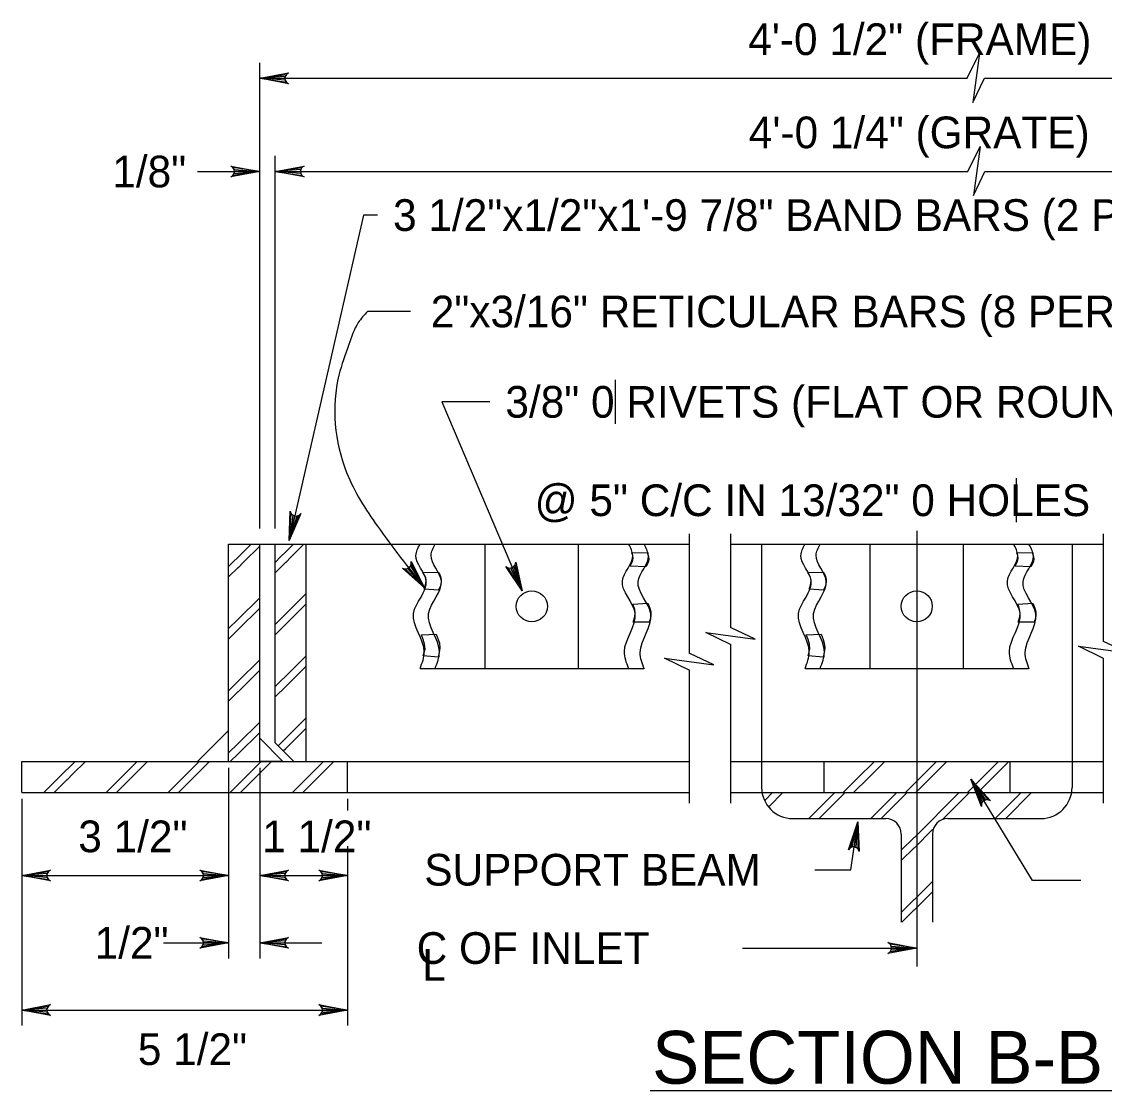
# Model space of a CAD drawing. Extents: x 0.71 to 8.05, y -5.67 to 4.31.
# Drawn here: x 0.931 to 2.982, y -3.979 to -1.955 of the extents above; entities that cross this region are included whole.
import ezdxf

# ---------------------------------------------------------------- set-up
doc = ezdxf.new("R2010")
doc.units = 0
for name, color, linetype in [('DETL-DIMS', 7, 'Continuous'), ('DETL-LINE', 7, 'Continuous'), ('DETL-NOTE', 7, 'Continuous'), ('DETL-PATT', 7, 'Continuous'), ('DETL-TITL', 7, 'Continuous')]:
    doc.layers.add(name, color=color, linetype=linetype)

msp = doc.modelspace()

# ---------------------------------------------------------------- linework, layer by layer
at = {"layer": 'DETL-DIMS'}
for p, q in [((1.382, -2.9151), (1.382, -2.0328)), ((1.382, -2.0622), (2.7227, -2.0622)), ((2.755, -2.0622), (3.8721, -2.0622)), ((1.4114, -2.9151), (1.4114, -2.2093)), ((1.2643, -2.2387), (1.382, -2.2387)), ((1.4114, -2.2387), (2.7238, -2.2387)), ((2.7562, -2.2387), (3.8427, -2.2387)), ((1.5786, -2.3212), (1.4378, -2.9377)), ((1.605, -2.3212), (1.5786, -2.3212)), ((1.6677, -2.5038), (1.5862, -2.5038)), ((1.8181, -2.6749), (1.7268, -2.6749)), ((1.7268, -2.6749), (1.8794, -3.033)), ((2.627, -2.9192), (2.627, -3.7442)), ((1.3231, -3.3681), (1.3231, -3.7289)), ((1.382, -3.3681), (1.382, -3.7289)), ((2.8464, -3.5814), (2.7297, -3.3893)), ((0.931, -3.4269), (0.931, -3.8563)), ((1.5486, -3.4269), (1.5486, -3.4486)), ((2.5023, -3.5611), (2.5155, -3.4706)), ((1.5486, -3.5162), (1.5486, -3.6334)), ((2.4338, -3.5611), (2.5023, -3.5611)), ((0.931, -3.572), (1.3231, -3.572)), ((1.382, -3.572), (1.5486, -3.572)), ((2.9376, -3.5814), (2.8462, -3.5814)), ((1.5486, -3.6334), (1.5486, -3.8563)), ((1.2, -3.6995), (1.3231, -3.6995)), ((1.382, -3.6995), (1.4996, -3.6995)), ((2.297, -3.7094), (2.627, -3.7094)), ((0.931, -3.8269), (1.5486, -3.8269))]:
    msp.add_line(p, q, dxfattribs=at)
for points in [[(2.7227, -2.0622), (2.746, -2.0145), (2.7333, -2.1078), (2.755, -2.0622)], [(1.382, -2.0622), (1.4368, -2.0519), (1.4326, -2.0548), (1.4304, -2.0585), (1.4297, -2.0622), (1.4304, -2.0659), (1.4326, -2.0695), (1.4368, -2.0725), (1.382, -2.0622), (1.4326, -2.0695), (1.4304, -2.0659), (1.382, -2.0622), (1.4297, -2.0622), (1.4304, -2.0585), (1.382, -2.0622), (1.4326, -2.0548)], [(2.7238, -2.2388), (2.7471, -2.1911), (2.7344, -2.2844), (2.7561, -2.2388)], [(1.382, -2.2387), (1.3271, -2.2489), (1.3313, -2.246), (1.3335, -2.2423), (1.3342, -2.2387), (1.3335, -2.235), (1.3313, -2.2313), (1.3271, -2.2284), (1.382, -2.2387), (1.3313, -2.2313), (1.3335, -2.235), (1.382, -2.2387), (1.3342, -2.2387), (1.3335, -2.2423), (1.382, -2.2387), (1.3313, -2.246)], [(1.4114, -2.2387), (1.4662, -2.2284), (1.462, -2.2313), (1.4598, -2.235), (1.4592, -2.2387), (1.4598, -2.2423), (1.462, -2.246), (1.4662, -2.2489), (1.4114, -2.2387), (1.462, -2.246), (1.4598, -2.2423), (1.4114, -2.2387), (1.4592, -2.2387), (1.4598, -2.235), (1.4114, -2.2387), (1.462, -2.2313)], [(1.4378, -2.9377), (1.44, -2.882), (1.4419, -2.8868), (1.445, -2.8897), (1.4484, -2.8911), (1.4521, -2.8914), (1.4562, -2.89), (1.46, -2.8866), (1.4378, -2.9377), (1.4562, -2.89), (1.4521, -2.8914), (1.4378, -2.9377), (1.4484, -2.8911), (1.445, -2.8897), (1.4378, -2.9377), (1.4419, -2.8868)], [(1.6941, -3.0271), (1.6527, -2.9897), (1.6576, -2.9913), (1.6618, -2.9908), (1.6651, -2.9891), (1.6677, -2.9863), (1.6693, -2.9824), (1.669, -2.9772), (1.6941, -3.0271), (1.6693, -2.9824), (1.6677, -2.9863), (1.6941, -3.0271), (1.6651, -2.9891), (1.6618, -2.9908), (1.6941, -3.0271), (1.6576, -2.9913)], [(1.8794, -3.033), (1.8485, -2.9866), (1.8528, -2.9894), (1.857, -2.9899), (1.8607, -2.9891), (1.8638, -2.987), (1.8663, -2.9836), (1.8674, -2.9786), (1.8794, -3.033), (1.8663, -2.9836), (1.8638, -2.987), (1.8794, -3.033), (1.8607, -2.9891), (1.857, -2.9899), (1.8794, -3.033), (1.8528, -2.9894)], [(2.7297, -3.3893), (2.7669, -3.4308), (2.7622, -3.4287), (2.7579, -3.4287), (2.7545, -3.4301), (2.7517, -3.4325), (2.7497, -3.4363), (2.7493, -3.4414), (2.7297, -3.3893), (2.7497, -3.4363), (2.7517, -3.4325), (2.7297, -3.3893), (2.7545, -3.4301), (2.7579, -3.4287), (2.7297, -3.3893), (2.7622, -3.4287)], [(2.5155, -3.4706), (2.5177, -3.5263), (2.5154, -3.5217), (2.5121, -3.519), (2.5086, -3.5178), (2.5048, -3.5179), (2.5009, -3.5196), (2.4974, -3.5233), (2.5155, -3.4706), (2.5009, -3.5196), (2.5048, -3.5179), (2.5155, -3.4706), (2.5086, -3.5178), (2.5121, -3.519), (2.5155, -3.4706), (2.5154, -3.5217)], [(0.931, -3.572), (0.9858, -3.5617), (0.9816, -3.5646), (0.9794, -3.5683), (0.9788, -3.572), (0.9794, -3.5757), (0.9816, -3.5794), (0.9858, -3.5823), (0.931, -3.572), (0.9816, -3.5794), (0.9794, -3.5757), (0.931, -3.572), (0.9788, -3.572), (0.9794, -3.5683), (0.931, -3.572), (0.9816, -3.5646)], [(1.3231, -3.572), (1.2683, -3.5823), (1.2725, -3.5794), (1.2747, -3.5757), (1.2753, -3.572), (1.2747, -3.5683), (1.2725, -3.5646), (1.2683, -3.5617), (1.3231, -3.572), (1.2725, -3.5646), (1.2747, -3.5683), (1.3231, -3.572), (1.2753, -3.572), (1.2747, -3.5757), (1.3231, -3.572), (1.2725, -3.5794)], [(1.382, -3.572), (1.4368, -3.5617), (1.4326, -3.5646), (1.4304, -3.5683), (1.4297, -3.572), (1.4304, -3.5757), (1.4326, -3.5794), (1.4368, -3.5823), (1.382, -3.572), (1.4326, -3.5794), (1.4304, -3.5757), (1.382, -3.572), (1.4297, -3.572), (1.4304, -3.5683), (1.382, -3.572), (1.4326, -3.5646)], [(1.5486, -3.572), (1.4938, -3.5823), (1.498, -3.5794), (1.5002, -3.5757), (1.5008, -3.572), (1.5002, -3.5683), (1.498, -3.5646), (1.4938, -3.5617), (1.5486, -3.572), (1.498, -3.5646), (1.5002, -3.5683), (1.5486, -3.572), (1.5008, -3.572), (1.5002, -3.5757), (1.5486, -3.572), (1.498, -3.5794)], [(1.3231, -3.6995), (1.2683, -3.7097), (1.2725, -3.7068), (1.2747, -3.7031), (1.2753, -3.6995), (1.2747, -3.6958), (1.2725, -3.6921), (1.2683, -3.6892), (1.3231, -3.6995), (1.2725, -3.6921), (1.2747, -3.6958), (1.3231, -3.6995), (1.2753, -3.6995), (1.2747, -3.7031), (1.3231, -3.6995), (1.2725, -3.7068)], [(1.382, -3.6995), (1.4368, -3.6892), (1.4326, -3.6921), (1.4304, -3.6958), (1.4297, -3.6995), (1.4304, -3.7031), (1.4326, -3.7068), (1.4368, -3.7097), (1.382, -3.6995), (1.4326, -3.7068), (1.4304, -3.7031), (1.382, -3.6995), (1.4297, -3.6995), (1.4304, -3.6958), (1.382, -3.6995), (1.4326, -3.6921)], [(2.627, -3.7094), (2.5722, -3.7197), (2.5764, -3.7167), (2.5786, -3.7131), (2.5793, -3.7094), (2.5786, -3.7057), (2.5764, -3.702), (2.5722, -3.6991), (2.627, -3.7094), (2.5764, -3.702), (2.5786, -3.7057), (2.627, -3.7094), (2.5793, -3.7094), (2.5786, -3.7131), (2.627, -3.7094), (2.5764, -3.7167)], [(0.931, -3.8269), (0.9858, -3.8166), (0.9816, -3.8195), (0.9794, -3.8232), (0.9788, -3.8269), (0.9794, -3.8306), (0.9816, -3.8343), (0.9858, -3.8372), (0.931, -3.8269), (0.9816, -3.8343), (0.9794, -3.8306), (0.931, -3.8269), (0.9788, -3.8269), (0.9794, -3.8232), (0.931, -3.8269), (0.9816, -3.8195)], [(1.5486, -3.8269), (1.4938, -3.8372), (1.498, -3.8343), (1.5002, -3.8306), (1.5008, -3.8269), (1.5002, -3.8232), (1.498, -3.8195), (1.4938, -3.8166), (1.5486, -3.8269), (1.498, -3.8195), (1.5002, -3.8232), (1.5486, -3.8269), (1.5008, -3.8269), (1.5002, -3.8306), (1.5486, -3.8269), (1.498, -3.8343)]]:
    msp.add_lwpolyline(points, dxfattribs=at)
msp.add_spline([(1.5862, -2.5038), (1.5688, -2.5249), (1.5506, -2.5666), (1.5321, -2.6241), (1.5467, -2.8089), (1.6053, -2.9106), (1.6941, -3.0271)], degree=3, dxfattribs=at)
at = {"layer": 'DETL-LINE'}
for p, q in [((2.1957, -2.9249), (2.1957, -3.1516)), ((2.2741, -2.9249), (2.2741, -3.1027)), ((2.98, -2.9249), (2.98, -3.1291)), ((1.3231, -3.3563), (1.3231, -2.9445)), ((1.3231, -2.9445), (2.1957, -2.9445)), ((1.382, -3.3563), (1.382, -2.9445)), ((1.4114, -3.321), (1.4114, -2.9445)), ((1.4702, -3.3563), (1.4702, -2.9445)), ((1.8094, -3.1798), (1.8094, -2.9445)), ((1.9859, -3.1798), (1.9859, -2.9445)), ((2.2741, -2.9445), (2.98, -2.9445)), ((2.3329, -2.9445), (2.3329, -3.4053)), ((2.5388, -3.1798), (2.5388, -2.9445)), ((2.7153, -3.1798), (2.7153, -2.9445)), ((2.9212, -2.9445), (2.9212, -3.4053)), ((2.2741, -3.1352), (2.2741, -3.4347)), ((2.98, -3.1612), (2.98, -3.4347)), ((1.6859, -3.1798), (2.1094, -3.1798)), ((2.1957, -3.1834), (2.1957, -3.4347)), ((2.4153, -3.1798), (2.8388, -3.1798)), ((1.4467, -3.3563), (1.4114, -3.321)), ((0.931, -3.4151), (0.931, -3.3563)), ((0.931, -3.3563), (2.1957, -3.3563)), ((1.5486, -3.4151), (1.5486, -3.3563)), ((2.2741, -3.3563), (2.98, -3.3563)), ((2.4506, -3.3563), (2.4506, -3.4151)), ((2.8035, -3.3563), (2.8035, -3.4151)), ((0.931, -3.4151), (2.1957, -3.4151)), ((2.2741, -3.4151), (2.98, -3.4151)), ((2.3918, -3.4642), (2.5682, -3.4642)), ((2.6859, -3.4642), (2.8623, -3.4642)), ((2.5976, -3.4936), (2.5976, -3.6602)), ((2.6565, -3.4936), (2.6565, -3.6602))]:
    msp.add_line(p, q, dxfattribs=at)
for points in [[(2.087, -2.9606), (2.1161, -2.9601), (2.1181, -2.9658), (2.1195, -2.9724), (2.1188, -2.977), (2.1163, -2.9829), (2.1137, -2.9872), (2.0837, -2.986), (2.0883, -2.9775), (2.0897, -2.9712), (2.089, -2.9659)], [(2.8164, -2.9606), (2.8455, -2.9601), (2.8476, -2.9658), (2.8489, -2.9724), (2.8482, -2.977), (2.8457, -2.9829), (2.8431, -2.9872), (2.8131, -2.986), (2.8177, -2.9775), (2.8191, -2.9712), (2.8184, -2.9659)], [(1.6914, -2.998), (1.72, -2.9978), (1.7237, -3.0041), (1.726, -3.011), (1.7259, -3.0173), (1.7241, -3.0246), (1.721, -3.0319), (1.6935, -3.0297), (1.6964, -3.0219), (1.6976, -3.0134), (1.6965, -3.0074), (1.6944, -3.0029)], [(2.4208, -2.998), (2.4494, -2.9978), (2.4531, -3.0041), (2.4554, -3.011), (2.4553, -3.0173), (2.4535, -3.0246), (2.4504, -3.0319), (2.4229, -3.0297), (2.4258, -3.0219), (2.427, -3.0134), (2.4259, -3.0074), (2.4238, -3.0029)], [(2.0889, -3.058), (2.1173, -3.0565), (2.1212, -3.0657), (2.1229, -3.0729), (2.1229, -3.0807), (2.1212, -3.0884), (2.12, -3.0922), (2.0898, -3.0919), (2.0926, -3.0823), (2.0933, -3.0754), (2.0925, -3.0682), (2.0904, -3.0615)], [(2.8183, -3.058), (2.8467, -3.0565), (2.8506, -3.0657), (2.8523, -3.0729), (2.8523, -3.0807), (2.8506, -3.0884), (2.8494, -3.0922), (2.8192, -3.0919), (2.822, -3.0823), (2.8227, -3.0754), (2.8219, -3.0682), (2.8198, -3.0615)], [(1.692, -3.1558), (1.6952, -3.1431), (1.6941, -3.1337), (1.6917, -3.1249), (1.6883, -3.1165), (1.7163, -3.115), (1.7204, -3.125), (1.7224, -3.1321), (1.7234, -3.1407), (1.7222, -3.1495), (1.7199, -3.1585)], [(2.4214, -3.1558), (2.4246, -3.1431), (2.4235, -3.1337), (2.4211, -3.1249), (2.4177, -3.1165), (2.4457, -3.115), (2.4498, -3.125), (2.4518, -3.1321), (2.4528, -3.1407), (2.4516, -3.1495), (2.4493, -3.1585)], [(1.3231, -3.2975), (1.2643, -3.3563), (1.3231, -3.3563)], [(1.382, -3.3122), (1.4261, -3.3563), (1.382, -3.3563)]]:
    msp.add_lwpolyline(points, close=True, dxfattribs=at)
for points in [[(2.2751, -3.1353), (2.2275, -3.1119), (2.3207, -3.1246), (2.2751, -3.1029)], [(2.981, -3.1611), (2.9334, -3.1378), (3.0266, -3.1505), (2.981, -3.1288)], [(2.1967, -3.1838), (2.149, -3.1605), (2.2423, -3.1732), (2.1967, -3.1515)]]:
    msp.add_lwpolyline(points, dxfattribs=at)
for centre in [(1.8976, -3.0622), (2.627, -3.0622)]:
    msp.add_circle(centre, 0.0294, dxfattribs=at)
for centre, radius, start, end in [((2.3918, -3.4053), 0.0588, 180, 270), ((2.8623, -3.4053), 0.0588, 270, 0), ((2.5682, -3.4936), 0.0294, 0, 90), ((2.6859, -3.4936), 0.0294, 90, 180)]:
    msp.add_arc(centre, radius, start, end, dxfattribs=at)
for points in [[(1.6859, -3.1798), (1.6939, -3.1486), (1.6736, -3.0756), (1.6976, -3.0139), (1.6781, -2.9658), (1.6859, -2.9445)], [(1.7145, -3.1797), (1.7224, -3.1485), (1.7021, -3.0755), (1.7262, -3.0138), (1.7067, -2.9656), (1.7145, -2.9444)], [(2.081, -3.1796), (2.073, -3.1483), (2.0933, -3.0753), (2.0693, -3.0137), (2.0888, -2.9655), (2.081, -2.9443)], [(2.1108, -3.1811), (2.1028, -3.1498), (2.1231, -3.0769), (2.0991, -3.0152), (2.1186, -2.967), (2.1108, -2.9458)], [(2.4153, -3.1798), (2.4233, -3.1486), (2.403, -3.0756), (2.427, -3.0139), (2.4075, -2.9658), (2.4153, -2.9445)], [(2.4439, -3.1797), (2.4519, -3.1485), (2.4316, -3.0755), (2.4556, -3.0138), (2.4361, -2.9656), (2.4439, -2.9444)], [(2.8104, -3.1796), (2.8024, -3.1483), (2.8227, -3.0753), (2.7987, -3.0137), (2.8182, -2.9655), (2.8104, -2.9443)], [(2.8402, -3.1811), (2.8322, -3.1498), (2.8525, -3.0769), (2.8285, -3.0152), (2.848, -2.967), (2.8402, -2.9458)]]:
    msp.add_spline(points, degree=3, dxfattribs=at)
at = {"layer": 'DETL-NOTE'}
for p, q in [((2.0558, -2.6333), (2.0558, -2.7166)), ((2.8153, -2.8196), (2.8153, -2.9029))]:
    msp.add_line(p, q, dxfattribs=at)
at = {"layer": 'DETL-PATT'}
for p, q in [((1.3415, -2.9689), (1.3659, -2.9445)), ((1.3513, -2.9787), (1.382, -2.9481)), ((1.4318, -2.9589), (1.4461, -2.9445)), ((1.4416, -2.9687), (1.4657, -2.9445)), ((1.3312, -2.9787), (1.341, -2.9689)), ((1.4114, -2.9789), (1.4215, -2.9687)), ((1.4215, -2.9687), (1.4314, -2.9589)), ((1.4416, -2.9687), (1.4314, -2.9789)), ((1.3231, -2.9868), (1.3312, -2.9787)), ((1.3231, -3.0064), (1.341, -2.9885)), ((1.3513, -2.9787), (1.341, -2.989)), ((1.4114, -2.9985), (1.4314, -2.9785)), ((1.3415, -3.0866), (1.382, -3.0461)), ((1.4318, -3.0765), (1.4702, -3.0381)), ((1.382, -3.0657), (1.3415, -3.1062)), ((1.4114, -3.0965), (1.4314, -3.0765)), ((1.4702, -3.0577), (1.4318, -3.0961)), ((1.3231, -3.1045), (1.341, -3.0866)), ((1.4114, -3.1161), (1.4314, -3.0961)), ((1.3231, -3.1241), (1.341, -3.1062)), ((1.4318, -3.1942), (1.4702, -3.1558)), ((1.3415, -3.2042), (1.382, -3.1637)), ((1.4416, -3.204), (1.4702, -3.1754)), ((1.3513, -3.214), (1.382, -3.1834)), ((1.4215, -3.204), (1.4314, -3.1942)), ((1.3231, -3.2221), (1.3312, -3.214)), ((1.3312, -3.214), (1.341, -3.2042)), ((1.3513, -3.214), (1.341, -3.2243)), ((1.4114, -3.2142), (1.4215, -3.204)), ((1.4114, -3.2338), (1.4314, -3.2138)), ((1.4416, -3.204), (1.4314, -3.2142)), ((1.3231, -3.2417), (1.341, -3.2238)), ((1.3415, -3.3219), (1.382, -3.2814)), ((1.4318, -3.3118), (1.4702, -3.2734)), ((1.382, -3.301), (1.3415, -3.3415)), ((1.4702, -3.293), (1.4318, -3.3314)), ((1.3231, -3.3398), (1.341, -3.3219)), ((1.4168, -3.3264), (1.4314, -3.3118)), ((1.3262, -3.3563), (1.341, -3.3415)), ((1.4266, -3.3362), (1.4314, -3.3314)), ((1.0178, -3.3706), (1.0321, -3.3563)), ((1.0276, -3.3804), (1.0517, -3.3563)), ((1.1257, -3.3804), (1.1497, -3.3563)), ((1.1453, -3.3804), (1.1693, -3.3563)), ((1.2433, -3.3804), (1.2674, -3.3563)), ((1.2629, -3.3804), (1.287, -3.3563)), ((1.361, -3.3804), (1.385, -3.3563)), ((1.3806, -3.3804), (1.4046, -3.3563)), ((1.4786, -3.3804), (1.5027, -3.3563)), ((1.4982, -3.3804), (1.5223, -3.3563)), ((2.5357, -3.3672), (2.5466, -3.3563)), ((2.5455, -3.377), (2.5662, -3.3563)), ((2.6435, -3.377), (2.6642, -3.3563)), ((2.6631, -3.377), (2.6839, -3.3563)), ((2.7612, -3.377), (2.7819, -3.3563)), ((2.7808, -3.377), (2.8015, -3.3563)), ((0.9728, -3.4151), (1.0076, -3.3804)), ((1.0076, -3.3804), (1.0174, -3.3706)), ((1.0276, -3.3804), (1.0174, -3.3906)), ((1.0909, -3.4151), (1.1257, -3.3804)), ((1.1453, -3.3804), (1.1105, -3.4151)), ((1.2086, -3.4151), (1.2433, -3.3804)), ((1.2282, -3.4151), (1.2629, -3.3804)), ((1.3262, -3.4151), (1.361, -3.3804)), ((1.3458, -3.4151), (1.3806, -3.3804)), ((1.4439, -3.4151), (1.4786, -3.3804)), ((1.4635, -3.4151), (1.4982, -3.3804)), ((2.4873, -3.4151), (2.5254, -3.377)), ((2.5254, -3.377), (2.5352, -3.3672)), ((2.5455, -3.377), (2.5352, -3.3873)), ((2.6054, -3.4151), (2.6435, -3.377)), ((2.6631, -3.377), (2.625, -3.4151)), ((2.7231, -3.4151), (2.7612, -3.377)), ((2.7427, -3.4151), (2.7808, -3.377)), ((0.9924, -3.4151), (1.0174, -3.3902)), ((2.5069, -3.4151), (2.5352, -3.3868)), ((2.3397, -3.4292), (2.3538, -3.4151)), ((2.3472, -3.4413), (2.3734, -3.4151)), ((2.4224, -3.4642), (2.4714, -3.4151)), ((2.442, -3.4642), (2.491, -3.4151)), ((2.54, -3.4642), (2.589, -3.4151)), ((2.5596, -3.4642), (2.6087, -3.4151)), ((2.6224, -3.4998), (2.7071, -3.4151)), ((2.7267, -3.4151), (2.6762, -3.4656)), ((2.7758, -3.4642), (2.8248, -3.4151)), ((2.7954, -3.4642), (2.8444, -3.4151)), ((2.6569, -3.485), (2.6224, -3.5195)), ((2.5976, -3.5242), (2.622, -3.4998)), ((2.5976, -3.5438), (2.622, -3.5195)), ((2.6224, -3.6175), (2.6565, -3.5835)), ((2.6322, -3.6273), (2.6565, -3.6031)), ((2.5976, -3.6418), (2.6122, -3.6273)), ((2.6122, -3.6273), (2.622, -3.6175)), ((2.6322, -3.6273), (2.622, -3.6375)), ((2.5989, -3.6602), (2.622, -3.6371))]:
    msp.add_line(p, q, dxfattribs=at)
at = {"layer": 'DETL-TITL'}
msp.add_line((2.1217, -3.9789), (3.1324, -3.9789), dxfattribs=at)

# ---------------------------------------------------------------- texts
at = {"layer": 'DETL-NOTE'}
for s, p in [('4\'-0 1/2" (FRAME)', (2.3077, -2.0181)), ('4\'-0 1/4" (GRATE)', (2.3088, -2.1946)), ('1/8"', (1.1027, -2.2687)), ('3 1/2"x1/2"x1\'-9 7/8" BAND BARS (2 PER GRATE)', (1.6347, -2.3512)), ('2"x3/16" RETICULAR BARS (8 PER GRATE)', (1.7061, -2.5338)), ('3/8" 0 RIVETS (FLAT OR ROUND HEAD)', (1.8475, -2.7049)), ('@ 5" C/C IN 13/32" 0 HOLES', (1.9029, -2.8913)), ('3 1/2"', (1.0383, -3.5279)), ('1 1/2"', (1.3868, -3.5279)), ('SUPPORT BEAM', (1.6939, -3.5911)), ('1/2"', (1.0693, -3.7295)), ('C OF INLET', (1.6794, -3.7394)), ('L', (1.6898, -3.7714)), ('5 1/2"', (1.1511, -3.931))]:
    msp.add_text(s, height=0.06, dxfattribs=at).set_placement(p)
at = {"layer": 'DETL-TITL'}
msp.add_text('SECTION B-B', height=0.1, dxfattribs=at).set_placement((2.1255, -3.9663))

doc.saveas('drawing.dxf')
